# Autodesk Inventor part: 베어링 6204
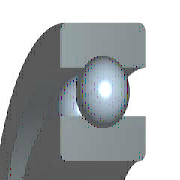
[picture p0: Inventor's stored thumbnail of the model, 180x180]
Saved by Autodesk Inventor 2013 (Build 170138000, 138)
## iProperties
Created: 2012-02
Part Number: 베어링 6204
Material: 강철, 연강
Description: 깊은 그루브 볼 베어링
Document SubType Name: Modeling
Standard: KS B 2023
Designer: mduedu
Standards Organization: KS
Language: ko-KR
Size Designation: 6203 - 17 x 40 x 12
Categories: <MemberInstance><Categories><Category DisplayName="샤프트 부품" InternalName="7f7aeb1f-a693-4053-b835-cee3144e0d98" Mnemonic="SHFT"><Category DisplayName="베어링" Inter
Density: 1 g/cm^3
IsCustomPart: 1
Author: mduedu
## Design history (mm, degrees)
sketch "스케치" dims "d0" = 7.02 (= -0.26 x WD + 0.26 x BD)
  geometry: L1 (3.49, 16.75)-(10.51, 16.75); L2 (7, 16.75)-(7, 13.24); L3 (7, 16.75)-(7, 20.26); L4 (4.392, 14.401)-(0, 14.401); L5 (0, 10)-(14, 10); L6 (4.392, 19.099)-(0, 19.099); L7 (0, 23.5)-(14, 23.5); L8 (14, 10)-(14, 14.401); L9 (9.608, 14.401)-(14, 14.401); L10 (9.608, 19.099)-(14, 19.099); L11 (14, 23.5)-(14, 19.099); L12 (-2.4, 0)-(14.4, 0) reference; L13 (0, 7.3)-(0, 26.2) reference
  constraints: 22 end point, 4 point on line, 2 collinear, 2 perpendicular, 2 symmetric about line, 1 midpoint, 1 parallel, 14 other
  dimensions: "d9" = 20 diameter of L5 L12 (= WD); "d11" = 47 diameter of L7 L12 (= BD); "d12" = 14 distance between parallel lines of L8 L13 (= KB); "d13" = 28.802 diameter of L9 L12 (= 0.326 x BD + 0.674 x WD)
revolve "본체" stored, may be unused: angle "d6" = 90 deg
revolve "볼" stored, may be unused: angle "d7" = 90 deg
pattern_circular "IDS_ARRAYBALL[SIMPL:T]" dims angle "d3" = 360 deg
body "Solid1"
fillet "모깎기1" dims "d1" = 1 (= KRS)
other parameters: "WD" = 20 [user parameter; used in 5 equation terms], "BD" = 47 [user parameter; used in 5 equation terms], "KB" = 14 [user parameter; used in 1 equation term], "KRS" = 1 [user parameter; used in 1 equation term], "d4" = 0, "d5" = 0, "d8" = 0, "d14" = 0, "d15" = 0, "BBA" = 0 [user parameter], "BC0" = 4750000 [user parameter], "BC" = 9560000 [user parameter], "BR" = 23.5 (= 0.5 x BD) [user parameter]
